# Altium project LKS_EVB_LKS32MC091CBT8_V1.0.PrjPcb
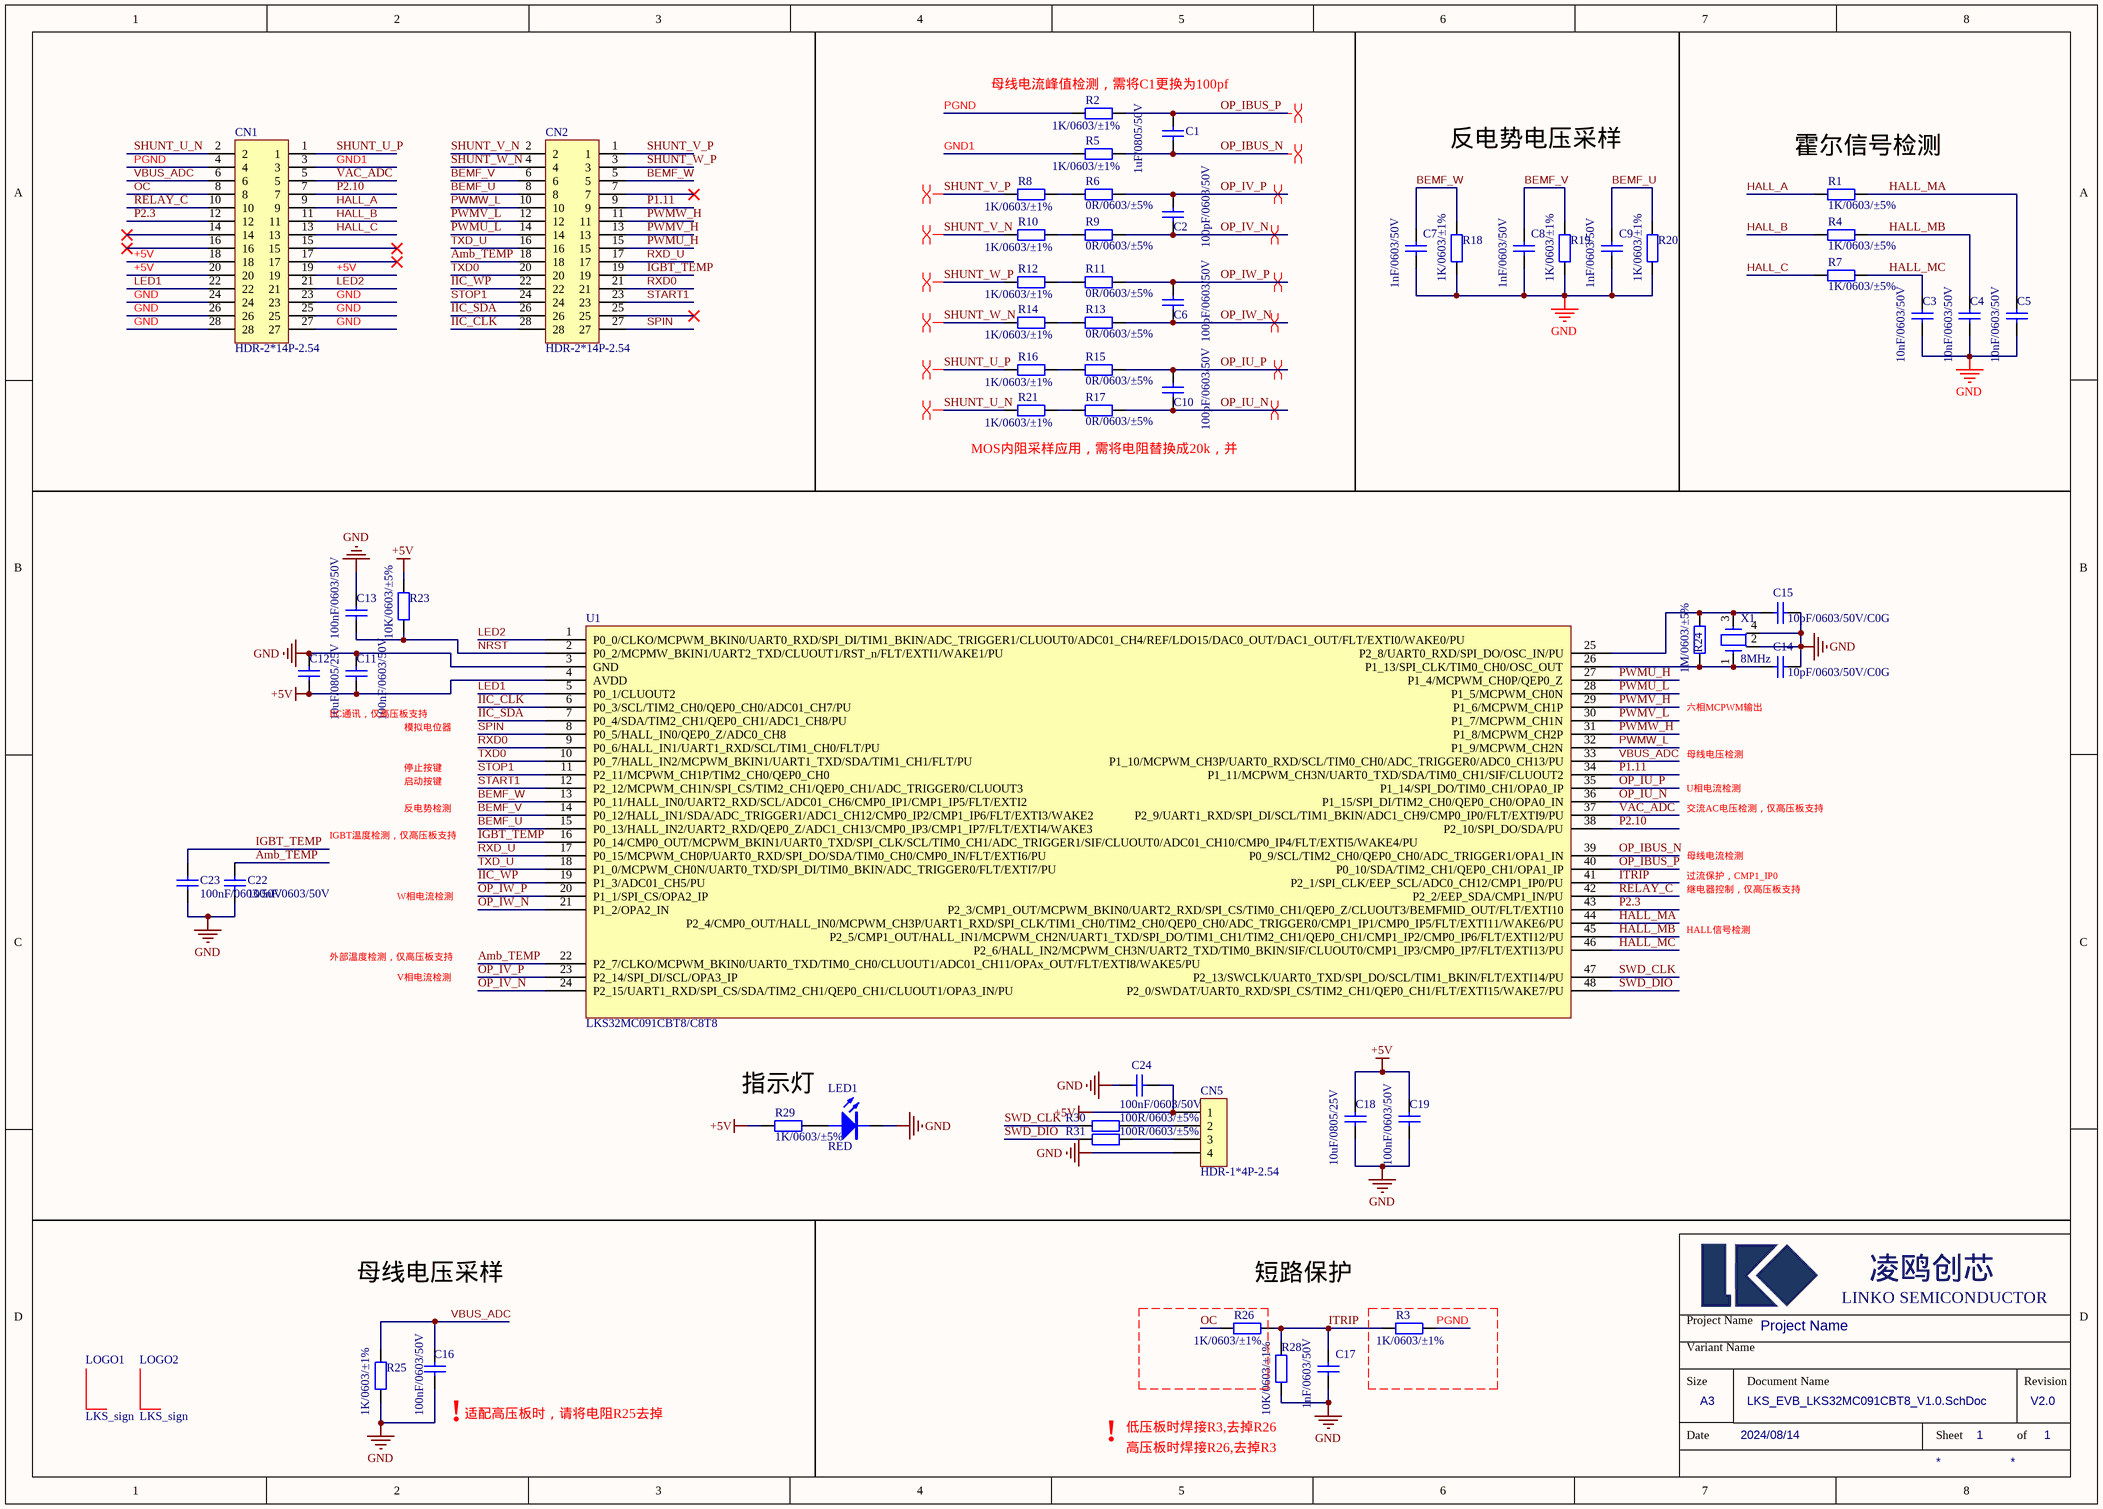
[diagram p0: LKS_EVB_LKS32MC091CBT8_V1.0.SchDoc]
1 sheet, 59 parts. Net scope: global (net labels, ports and power ports of the same name join across sheets).
Board file: LKS_EVB_LKS32MC091CBT8_V1.0.PcbDoc

## Sheet LKS_EVB_LKS32MC091CBT8_V1.0.SchDoc
size A3; Date: 2024/08/14; Revision: V2.0; SheetNumber: 1; SheetTotal: 1; Variant Name: [No Variations]; Size: A3

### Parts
C1  1uF/0805/50V  [C0805S]
C2  100pF/0603/50V  [C0603S]
C3  10nF/0603/50V  [C0603S]
C4  10nF/0603/50V  [C0603S]
C5  10nF/0603/50V  [C0603S]
C6  100pF/0603/50V  [C0603S]
C7  1nF/0603/50V  [C0603S]
C8  1nF/0603/50V  [C0603S]
C9  1nF/0603/50V  [C0603S]
C10  100pF/0603/50V  [C0603S]
C11  100nF/0603/50V  [C0603S]
C12  10uF/0805/25V  [C0805S]
C13  100nF/0603/50V  [C0603S]
C14  10pF/0603/50V/C0G  [C0603S]  (no BOM)
C15  10pF/0603/50V/C0G  [C0603S]  (no BOM)
C16  100nF/0603/50V  [C0603S]
C17  1nF/0603/50V  [C0603S]
C18  10uF/0805/25V  [C0805S]
C19  100nF/0603/50V  [C0603S]
C22  100nF/0603/50V  [C0603S]
C23  100nF/0603/50V  [C0603S]
C24  100nF/0603/50V  [C0603S]
CN1  HDR-2*14P-2.54  [HDR2X14/2.54-F-B]
CN2  HDR-2*14P-2.54  [HDR2X14/2.54-F-B]
CN5  HDR-1*4P-2.54  [HDR-1*4P-2.54]
LED1  RED  [LED0603]
LOGO1  LKS_sign  [LKS_LOGO2]  (no BOM)
LOGO2  LKS_sign  [LKS_LOGO1]  (no BOM)
R1  1K/0603/±5%  [R0603S]
R2  1K/0603/±1%  [R0603S]
R3  1K/0603/±1%  [R0603S]
R4  1K/0603/±5%  [R0603S]
R5  1K/0603/±1%  [R0603S]
R6  0R/0603/±5%  [R0603S]
R7  1K/0603/±5%  [R0603S]
R8  1K/0603/±1%  [R0603S]
R9  0R/0603/±5%  [R0603S]
R10  1K/0603/±1%  [R0603S]
R11  0R/0603/±5%  [R0603S]
R12  1K/0603/±1%  [R0603S]
R13  0R/0603/±5%  [R0603S]
R14  1K/0603/±1%  [R0603S]
R15  0R/0603/±5%  [R0603S]
R16  1K/0603/±1%  [R0603S]
R17  0R/0603/±5%  [R0603S]
R18  1K/0603/±1%  [R0603S]
R19  1K/0603/±1%  [R0603S]
R20  1K/0603/±1%  [R0603S]
R21  1K/0603/±1%  [R0603S]
R23  10K/0603/±5%  [R0603S]
R24  1M/0603/±5%  [R0603S]
R25  1K/0603/±1%  [R0603S]
R26  1K/0603/±1%  [R0603S]
R28  10K/0603/±1%  [R0603S]
R29  1K/0603/±5%  [R0603S]
R30  100R/0603/±5%  [R0603S]
R31  100R/0603/±5%  [R0603S]
U1  LKS32MC091CBT8/C8T8  [TQFP48 7x7]
X1  8MHz  [XTAL-SMD3225]

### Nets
+5V: C11.1 C12.1 C18.2 C19.2 C24.1 CN1.18 CN1.19 CN1.20 CN5.1 R23.2 R29.1 U1.4(AVDD)
GND: C3.1 C4.1 C5.1 C7.1 C8.1 C9.1 C11.2 C12.2 C13.1 C14.1 C15.1 C16.1 C17.1 C18.1 C19.1 C22.1 C23.1 C24.2 CN1.23 CN1.24 CN1.25 CN1.26 CN1.27 CN1.28 CN5.4 LED1.2(K) R18.1 R19.1 R20.1 R25.1 R28.1 U1.3(GND) X1.2 X1.4
Amb_TEMP: C22.2 CN2.18 U1.22(P2_7/CLKO/MCPWM_BKIN0/UART0_TXD/TIM0_CH0/CLUOUT1/ADC01_CH11/OPAx_OUT/FLT/EXTI8/WAKE5/PU)
BEMF_U: C9.2 CN2.8 R20.2 U1.15(P0_13/HALL_IN2/UART2_RXD/QEP0_Z/ADC1_CH13/CMP0_IP3/CMP1_IP7/FLT/EXTI4/WAKE3)
BEMF_V: C8.2 CN2.6 R19.2 U1.14(P0_12/HALL_IN1/SDA/ADC_TRIGGER1/ADC1_CH12/CMP0_IP2/CMP1_IP6/FLT/EXTI3/WAKE2)
BEMF_W: C7.2 CN2.5 R18.2 U1.13(P0_11/HALL_IN0/UART2_RXD/SCL/ADC01_CH6/CMP0_IP1/CMP1_IP5/FLT/EXTI2)
GND1: CN1.3 R5.1
HALL_A: CN1.9 R1.1
HALL_B: CN1.11 R4.1
HALL_C: CN1.13 R7.1
HALL_MA: C5.2 R1.2 U1.44(P2_4/CMP0_OUT/HALL_IN0/MCPWM_CH3P/UART1_RXD/SPI_CLK/TIM1_CH0/TIM2_CH0/QEP0_CH0/ADC_TRIGGER0/CMP1_IP1/CMP0_IP5/FLT/EXTI11/WAKE6/PU)
HALL_MB: C4.2 R4.2 U1.45(P2_5/CMP1_OUT/HALL_IN1/MCPWM_CH2N/UART1_TXD/SPI_DO/TIM1_CH1/TIM2_CH1/QEP0_CH1/CMP1_IP2/CMP0_IP6/FLT/EXTI12/PU)
HALL_MC: C3.2 R7.2 U1.46(P2_6/HALL_IN2/MCPWM_CH3N/UART2_TXD/TIM0_BKIN/SIF/CLUOUT0/CMP1_IP3/CMP0_IP7/FLT/EXTI13/PU)
IGBT_TEMP: C23.2 CN2.19 U1.16(P0_14/CMP0_OUT/MCPWM_BKIN1/UART0_TXD/SPI_CLK/SCL/TIM0_CH1/ADC_TRIGGER1/SIF/CLUOUT0/ADC01_CH10/CMP0_IP4/FLT/EXTI5/WAKE4/PU)
IIC_CLK: CN2.28 U1.6(P0_3/SCL/TIM2_CH0/QEP0_CH0/ADC01_CH7/PU)
IIC_SDA: CN2.26 U1.7(P0_4/SDA/TIM2_CH1/QEP0_CH1/ADC1_CH8/PU)
IIC_WP: CN2.22 U1.19(P1_3/ADC01_CH5/PU)
ITRIP: C17.2 R3.1 R26.2 R28.2 U1.41(P2_1/SPI_CLK/EEP_SCL/ADC0_CH12/CMP1_IP0/PU)
LED1: CN1.22 U1.5(P0_1/CLUOUT2)
LED2: CN1.21 U1.1(P0_0/CLKO/MCPWM_BKIN0/UART0_RXD/SPI_DI/TIM1_BKIN/ADC_TRIGGER1/CLUOUT0/ADC01_CH4/REF/LDO15/DAC0_OUT/DAC1_OUT/FLT/EXTI0/WAKE0/PU)
NRST: C13.2 R23.1 U1.2(P0_2/MCPMW_BKIN1/UART2_TXD/CLUOUT1/RST_n/FLT/EXTI1/WAKE1/PU)
OC: CN1.8 R26.1
OP_IBUS_N: C1.1 R5.2 U1.39(P0_9/SCL/TIM2_CH0/QEP0_CH0/ADC_TRIGGER1/OPA1_IN)
OP_IBUS_P: C1.2 R2.2 U1.40(P0_10/SDA/TIM2_CH1/QEP0_CH1/OPA1_IP)
OP_IU_N: C10.1 R17.2 U1.36(P1_15/SPI_DI/TIM2_CH0/QEP0_CH0/OPA0_IN)
OP_IU_P: C10.2 R15.2 U1.35(P1_14/SPI_DO/TIM0_CH1/OPA0_IP)
OP_IV_N: C2.1 R9.2 U1.24(P2_15/UART1_RXD/SPI_CS/SDA/TIM2_CH1/QEP0_CH1/CLUOUT1/OPA3_IN/PU)
OP_IV_P: C2.2 R6.2 U1.23(P2_14/SPI_DI/SCL/OPA3_IP)
OP_IW_N: C6.1 R13.2 U1.21(P1_2/OPA2_IN)
OP_IW_P: C6.2 R11.2 U1.20(P1_1/SPI_CS/OPA2_IP)
P1.11: CN2.9 U1.34(P1_11/MCPWM_CH3N/UART0_TXD/SDA/TIM0_CH1/SIF/CLUOUT2)
P2.3: CN1.12 U1.43(P2_3/CMP1_OUT/MCPWM_BKIN0/UART2_RXD/SPI_CS/TIM0_CH1/QEP0_Z/CLUOUT3/BEMFMID_OUT/FLT/EXTI10)
P2.10: CN1.7 U1.38(P2_10/SPI_DO/SDA/PU)
PGND: CN1.4 R2.1 R3.2
PWMU_H: CN2.15 U1.27(P1_4/MCPWM_CH0P/QEP0_Z)
PWMU_L: CN2.14 U1.28(P1_5/MCPWM_CH0N)
PWMV_H: CN2.13 U1.29(P1_6/MCPWM_CH1P)
PWMV_L: CN2.12 U1.30(P1_7/MCPWM_CH1N)
PWMW_H: CN2.11 U1.31(P1_8/MCPWM_CH2P)
PWMW_L: CN2.10 U1.32(P1_9/MCPWM_CH2N)
RELAY_C: CN1.10 U1.42(P2_2/EEP_SDA/CMP1_IN/PU)
RXD0: CN2.21 U1.9(P0_6/HALL_IN1/UART1_RXD/SCL/TIM1_CH0/FLT/PU)
RXD_U: CN2.17 U1.17(P0_15/MCPWM_CH0P/UART0_RXD/SPI_DO/SDA/TIM0_CH0/CMP0_IN/FLT/EXTI6/PU)
SHUNT_U_N: CN1.2 R21.1
SHUNT_U_P: CN1.1 R16.1
SHUNT_V_N: CN2.2 R10.1
SHUNT_V_P: CN2.1 R8.1
SHUNT_W_N: CN2.4 R14.1
SHUNT_W_P: CN2.3 R12.1
SPIN: CN2.27 U1.8(P0_5/HALL_IN0/QEP0_Z/ADC0_CH8)
START1: CN2.23 U1.12(P2_12/MCPWM_CH1N/SPI_CS/TIM2_CH1/QEP0_CH1/ADC_TRIGGER0/CLUOUT3)
STOP1: CN2.24 U1.11(P2_11/MCPWM_CH1P/TIM2_CH0/QEP0_CH0)
SWD_CLK: R30.1 U1.47(P2_13/SWCLK/UART0_TXD/SPI_DO/SCL/TIM1_BKIN/FLT/EXTI14/PU)
SWD_DIO: R31.1 U1.48(P2_0/SWDAT/UART0_RXD/SPI_CS/TIM2_CH1/QEP0_CH1/FLT/EXTI15/WAKE7/PU)
TXD0: CN2.20 U1.10(P0_7/HALL_IN2/MCPWM_BKIN1/UART1_TXD/SDA/TIM1_CH1/FLT/PU)
TXD_U: CN2.16 U1.18(P1_0/MCPWM_CH0N/UART0_TXD/SPI_DI/TIM0_BKIN/ADC_TRIGGER0/FLT/EXTI7/PU)
VAC_ADC: CN1.5 U1.37(P2_9/UART1_RXD/SPI_DI/SCL/TIM1_BKIN/ADC1_CH9/CMP0_IP0/FLT/EXTI9/PU)
VBUS_ADC: C16.2 CN1.6 R25.2 U1.33(P1_10/MCPWM_CH3P/UART0_RXD/SCL/TIM0_CH0/ADC_TRIGGER0/ADC0_CH13/PU)
NetC14_2: C14.2 R24.2 U1.26(P1_13/SPI_CLK/TIM0_CH0/OSC_OUT) X1.1
NetC15_2: C15.2 R24.1 U1.25(P2_8/UART0_RXD/SPI_DO/OSC_IN/PU) X1.3
NetCN5_2: CN5.2 R30.2
NetCN5_3: CN5.3 R31.2
NetLED1_1: LED1.1(A) R29.2
NetR6_1: R6.1 R8.2
NetR9_1: R9.1 R10.2
NetR11_1: R11.1 R12.2
NetR13_1: R13.1 R14.2
NetR15_1: R15.1 R16.2
NetR17_1: R17.1 R21.2

Not connected (* = marked no-connect by the designer): CN1 14* 15* 16* 17*; CN2 7* 25*

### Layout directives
differential pair: OP_IBUS_N, OP_IBUS_P, OP_IU_N, OP_IU_P, OP_IV_N, OP_IV_P, OP_IW_N, OP_IW_P, SHUNT_U_N, SHUNT_U_P, SHUNT_V_N, SHUNT_V_P, SHUNT_W_N, SHUNT_W_P

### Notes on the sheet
- (near R2) 母线电流峰值检测，需将C1更换为100pf
- 反电势电压采样
- (near R1) 霍尔信号检测
- MOS内阻采样应用，需将电阻替换成20k，并
- IIC通讯，仅高压板支持
- 六相MCPWM输出
- 启动按键
- 停止按键
- 模拟电位器
- 母线电压检测
- IGBT温度检测，仅高压板支持
- 反电势检测
- 交流AC电压检测，仅高压板支持
- 母线电流检测
- U相电流检测
- W相电流检测
- 过流保护，CMP1_IP0
- 继电器控制，仅高压板支持
- 外部温度检测，仅高压板支持
- V相电流检测
- HALL信号检测
- (near R29) 指示灯
- 母线电压采样
- (near R26) 短路保护
- (near C16) !
- (near C16) 适配高压板时，请将电阻R25去掉
- !
- 低压板时焊接R3,去掉R26
- 高压板时焊接R26,去掉R3

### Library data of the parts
C1 = 贴片电容\1uF\0805\25V\K: 493950200049; SAP: 254219000249; WHP_P/N: CO00000000066
C2 C6 C10 = 贴片电容\100pF\0603\50V\K\X7R: 493950200009; SAP: 254219000227
C3-C5 = 贴片电容\10nF\0603\50V\K\X7R: 493950200014; SAP: 254219000228; WHP_P/N: CO00000000002
C7-C9 C17 = 贴片电容\1nF\0603\50V\K\X7R: WHP; WHP_P/N: CO00000000003
C11 C13 C16 C19 C22-C24 = 贴片电容\100nF\0603\50V\K\X7R: 493950200070; SAP: 254219000229; WHP_P/N: CO00000000001
C12 C18 = 贴片电容\10uF\0805\25V\K\X5R: 493950200052; SAP: 254219000500; WHP_P/N: CO00000000074
C14 C15 = 贴片电容\10pF\0603\50V\C0G: C1634
CN1 CN2 = 插座\排针\双排\2.54\180度\2*14PIN: C2894975
CN5 = 插座\排针\单排\2.54\180度\4PIN: 493930100259; SAP: 254279000323; WHP_P/N: 70C81A0001663
LED1 = 发光二极管\贴片\XY-DA0603HRK-620D\RED: 493920100058; SAP: 254269000193
R1 R4 R7 R29 = 贴片电阻\1K±5%\0603: 493960700021; SAP: 254209000293; WHP_P/N: RMFJ000000011
R2 R3 R5 R8 R10 R12 R14 R16 R18-R21 R25 R26 = 贴片电阻\1K±1%\0603: 493960700020; SAP: 254209000298; WHP_P/N: RMFF000000004
R6 R9 R11 R13 R15 R17 = 贴片电阻\0R±5%\0603: 493960700009; SAP: 254209000258; WHP_P/N: RMFF000000019
R23 = 贴片电阻\10K±5%\0603: 493960700034; SAP: 254209000276; WHP_P/N: RMFJ000000014
R24 = 贴片电阻\1M±5%\0603: 493960700050; SAP: 254209000299; WHP_P/N: RMFJ000000015
R28 = 贴片电阻\10K±1%\0603: 493960700033; SAP: 254209000275; WHP_P/N: RMFF000000008
R30 R31 = 贴片电阻\100R±5%\0603: 493960700012; SAP: 254209000265; WHP_P/N: RMFJ000000010
U1 = MCU\LKS32MC091CBT8/C8T8\TQFP48: 主频: 96MHz; FLASH: 128KB; RAM: 8KB; 封装: TQFP48; 工作电压: 2.5~5.5V; 工作温度: -40~105℃; 预驱: 类型/电流/电压; MCPWM: 8路/4对
X1 = 晶体\SMD3225\8.0MHz\12pF\±10ppm: C2973805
